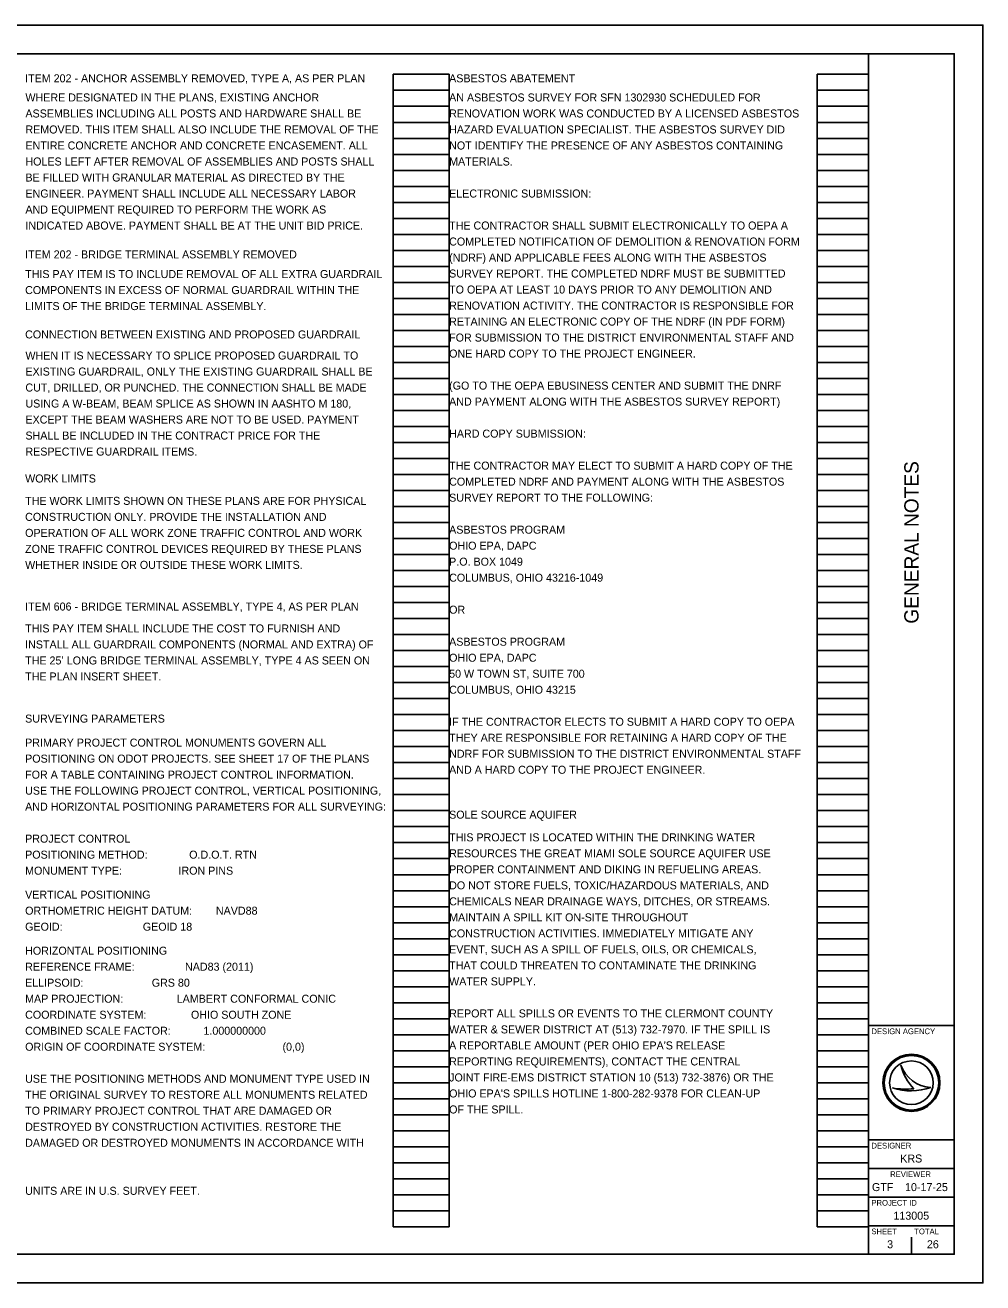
# Model space of a CAD drawing. Extents: x 0 to 78.9, y -24.2 to 22.
# Drawn here: x 17.24 to 34, y 0 to 22 of the extents above; entities that cross this region are included whole.
import ezdxf

# ---------------------------------------------------------------- set-up
doc = ezdxf.new("R2010")
doc.units = 0
for name, color, linetype in [('SH_Border', 7, 'Continuous'), ('SH_Cut_Line', 7, 'Continuous'), ('SH_Data', 7, 'Continuous'), ('SH_Text', 7, 'Continuous')]:
    doc.layers.add(name, color=color, linetype=linetype)

msp = doc.modelspace()

# ---------------------------------------------------------------- linework, layer by layer
at = {"layer": 'SH_Border'}
for p, q in [((32, 0.5), (32, 21.5)), ((32, 4.5), (33.5, 4.5)), ((32, 2.5), (33.5, 2.5)), ((32, 2), (33.5, 2)), ((32, 1.5), (33.5, 1.5)), ((32, 1), (33.5, 1))]:
    msp.add_line(p, q, dxfattribs=at)
msp.add_lwpolyline([(1.5, 21.5), (33.5, 21.5), (33.5, 0.5), (1.5, 0.5)], close=True, dxfattribs=at)
at = {"layer": 'SH_Cut_Line'}
msp.add_lwpolyline([(0, 0), (34, 0), (34, 22), (0, 22)], close=True, dxfattribs=at)
at = {"layer": 'SH_Data'}
for p, q in [((23.68, 0.98), (23.68, 21.14)), ((23.68, 21.14), (24.66, 21.14)), ((24.66, 0.98), (24.66, 21.14)), ((31.1, 0.98), (31.1, 21.14)), ((31.1, 21.14), (32, 21.14)), ((32, 0.98), (32, 21.14)), ((23.68, 20.86), (24.66, 20.86)), ((31.1, 20.86), (32, 20.86)), ((23.68, 20.58), (24.66, 20.58)), ((31.1, 20.58), (32, 20.58)), ((23.68, 20.3), (24.66, 20.3)), ((31.1, 20.3), (32, 20.3)), ((23.68, 20.02), (24.66, 20.02)), ((31.1, 20.02), (32, 20.02)), ((23.68, 19.74), (24.66, 19.74)), ((31.1, 19.74), (32, 19.74)), ((23.68, 19.46), (24.66, 19.46)), ((31.1, 19.46), (32, 19.46)), ((23.68, 19.18), (24.66, 19.18)), ((31.1, 19.18), (32, 19.18)), ((23.68, 18.9), (24.66, 18.9)), ((31.1, 18.9), (32, 18.9)), ((23.68, 18.62), (24.66, 18.62)), ((31.1, 18.62), (32, 18.62)), ((23.68, 18.34), (24.66, 18.34)), ((31.1, 18.34), (32, 18.34)), ((23.68, 18.06), (24.66, 18.06)), ((31.1, 18.06), (32, 18.06)), ((23.68, 17.78), (24.66, 17.78)), ((31.1, 17.78), (32, 17.78)), ((23.68, 17.5), (24.66, 17.5)), ((31.1, 17.5), (32, 17.5)), ((23.68, 17.22), (24.66, 17.22)), ((31.1, 17.22), (32, 17.22)), ((23.68, 16.94), (24.66, 16.94)), ((31.1, 16.94), (32, 16.94)), ((23.68, 16.66), (24.66, 16.66)), ((31.1, 16.66), (32, 16.66)), ((23.68, 16.38), (24.66, 16.38)), ((31.1, 16.38), (32, 16.38)), ((23.68, 16.1), (24.66, 16.1)), ((31.1, 16.1), (32, 16.1)), ((23.68, 15.82), (24.66, 15.82)), ((31.1, 15.82), (32, 15.82)), ((23.68, 15.54), (24.66, 15.54)), ((31.1, 15.54), (32, 15.54)), ((23.68, 15.26), (24.66, 15.26)), ((31.1, 15.26), (32, 15.26)), ((23.68, 14.98), (24.66, 14.98)), ((31.1, 14.98), (32, 14.98)), ((23.68, 14.7), (24.66, 14.7)), ((31.1, 14.7), (32, 14.7)), ((23.68, 14.42), (24.66, 14.42)), ((31.1, 14.42), (32, 14.42)), ((23.68, 14.14), (24.66, 14.14)), ((31.1, 14.14), (32, 14.14)), ((23.68, 13.86), (24.66, 13.86)), ((31.1, 13.86), (32, 13.86)), ((23.68, 13.58), (24.66, 13.58)), ((31.1, 13.58), (32, 13.58)), ((23.68, 13.3), (24.66, 13.3)), ((31.1, 13.3), (32, 13.3)), ((23.68, 13.02), (24.66, 13.02)), ((31.1, 13.02), (32, 13.02)), ((23.68, 12.74), (24.66, 12.74)), ((31.1, 12.74), (32, 12.74)), ((23.68, 12.46), (24.66, 12.46)), ((31.1, 12.46), (32, 12.46)), ((23.68, 12.18), (24.66, 12.18)), ((31.1, 12.18), (32, 12.18)), ((23.68, 11.9), (24.66, 11.9)), ((31.1, 11.9), (32, 11.9)), ((23.68, 11.62), (24.66, 11.62)), ((31.1, 11.62), (32, 11.62)), ((23.68, 11.34), (24.66, 11.34)), ((31.1, 11.34), (32, 11.34)), ((23.68, 11.06), (24.66, 11.06)), ((31.1, 11.06), (32, 11.06)), ((23.68, 10.78), (24.66, 10.78)), ((31.1, 10.78), (32, 10.78)), ((23.68, 10.5), (24.66, 10.5)), ((31.1, 10.5), (32, 10.5)), ((23.68, 10.22), (24.66, 10.22)), ((31.1, 10.22), (32, 10.22)), ((23.68, 9.94), (24.66, 9.94)), ((31.1, 9.94), (32, 9.94)), ((23.68, 9.66), (24.66, 9.66)), ((31.1, 9.66), (32, 9.66)), ((23.68, 9.38), (24.66, 9.38)), ((31.1, 9.38), (32, 9.38)), ((23.68, 9.1), (24.66, 9.1)), ((31.1, 9.1), (32, 9.1)), ((23.68, 8.82), (24.66, 8.82)), ((31.1, 8.82), (32, 8.82)), ((23.68, 8.54), (24.66, 8.54)), ((31.1, 8.54), (32, 8.54)), ((23.68, 8.26), (24.66, 8.26)), ((31.1, 8.26), (32, 8.26)), ((23.68, 7.98), (24.66, 7.98)), ((31.1, 7.98), (32, 7.98)), ((23.68, 7.7), (24.66, 7.7)), ((31.1, 7.7), (32, 7.7)), ((23.68, 7.42), (24.66, 7.42)), ((31.1, 7.42), (32, 7.42)), ((23.68, 7.14), (24.66, 7.14)), ((31.1, 7.14), (32, 7.14)), ((23.68, 6.86), (24.66, 6.86)), ((31.1, 6.86), (32, 6.86)), ((23.68, 6.58), (24.66, 6.58)), ((31.1, 6.58), (32, 6.58)), ((23.68, 6.3), (24.66, 6.3)), ((31.1, 6.3), (32, 6.3)), ((23.68, 6.02), (24.66, 6.02)), ((31.1, 6.02), (32, 6.02)), ((23.68, 5.74), (24.66, 5.74)), ((31.1, 5.74), (32, 5.74)), ((23.68, 5.46), (24.66, 5.46)), ((31.1, 5.46), (32, 5.46)), ((23.68, 5.18), (24.66, 5.18)), ((31.1, 5.18), (32, 5.18)), ((23.68, 4.9), (24.66, 4.9)), ((31.1, 4.9), (32, 4.9)), ((23.68, 4.62), (24.66, 4.62)), ((31.1, 4.62), (32, 4.62)), ((23.68, 4.34), (24.66, 4.34)), ((31.1, 4.34), (32, 4.34)), ((23.68, 4.06), (24.66, 4.06)), ((31.1, 4.06), (32, 4.06)), ((23.68, 3.78), (24.66, 3.78)), ((31.1, 3.78), (32, 3.78)), ((32.567, 3.81), (32.567, 3.81)), ((23.68, 3.5), (24.66, 3.5)), ((31.1, 3.5), (32, 3.5)), ((32.417, 3.41), (32.417, 3.41)), ((32.75, 3.5), (32.75, 3.5)), ((33.087, 3.419), (33.087, 3.419)), ((23.68, 3.22), (24.66, 3.22)), ((31.1, 3.22), (32, 3.22)), ((23.68, 2.94), (24.66, 2.94)), ((31.1, 2.94), (32, 2.94)), ((23.68, 2.66), (24.66, 2.66)), ((31.1, 2.66), (32, 2.66)), ((23.68, 2.38), (24.66, 2.38)), ((31.1, 2.38), (32, 2.38)), ((23.68, 2.1), (24.66, 2.1)), ((31.1, 2.1), (32, 2.1)), ((23.68, 1.82), (24.66, 1.82)), ((31.1, 1.82), (32, 1.82)), ((23.68, 1.54), (24.66, 1.54)), ((31.1, 1.54), (32, 1.54)), ((23.68, 1.26), (24.66, 1.26)), ((31.1, 1.26), (32, 1.26)), ((23.68, 0.98), (24.66, 0.98)), ((31.1, 0.98), (32, 0.98)), ((32.375, 0.675), (32.375, 0.675)), ((32.75, 0.5), (32.75, 0.8))]:
    msp.add_line(p, q, dxfattribs=at)
for radius in [0.5, 0.477, 0.477, 0.382]:
    msp.add_circle((32.75, 3.5), radius, dxfattribs=at)
for centre, radius, start, end in [((33.116, 3.998), 0.58, 198.9257, 198.9319), ((33.347, 3.97), 0.796, 191.6379, 191.6421), ((33.116, 3.998), 0.58, 198.9319, 267.1657), ((33.347, 3.97), 0.796, 191.6421, 226.0947), ((32.739, 4.37), 1.013, 251.4576, 290.0832), ((32.648, 4.654), 1.266, 259.4964, 259.4995), ((32.739, 4.37), 1.013, 251.4527, 251.4576), ((32.648, 4.654), 1.266, 259.4995, 276.6672)]:
    msp.add_arc(centre, radius, start, end, dxfattribs=at)

# ---------------------------------------------------------------- texts
msp.add_text('GENERAL NOTES', height=0.25, rotation=90, dxfattribs=at).set_placement((32.875, 11.531))
for s, height, p in [('DESIGN AGENCY', 0.1, (32.05, 4.35)), ('DESIGNER', 0.1, (32.05, 2.35)), ('KRS', 0.14, (32.554, 2.105)), ('REVIEWER', 0.1, (32.378, 1.85)), ('GTF', 0.14, (32.059, 1.605)), ('10-17-25', 0.14, (32.638, 1.605)), ('PROJECT ID', 0.1, (32.05, 1.35)), ('113005', 0.14, (32.435, 1.105)), ('SHEET', 0.1, (32.05, 0.85)), ('TOTAL', 0.1, (32.8, 0.85)), ('3', 0.14, (32.325, 0.605)), ('26', 0.14, (33.021, 0.605))]:
    msp.add_text(s, height=height, dxfattribs=at).set_placement(p)
at = {"layer": 'SH_Text'}
for s, p in [('ITEM 202 - ANCHOR ASSEMBLY REMOVED, TYPE A, AS PER PLAN', (17.24, 21)), ('ASBESTOS ABATEMENT', (24.66, 21)), ('WHERE DESIGNATED IN THE PLANS, EXISTING ANCHOR ', (17.245, 20.665)), ('AN ASBESTOS SURVEY FOR SFN 1302930 SCHEDULED FOR ', (24.66, 20.665)), ('ASSEMBLIES INCLUDING ALL POSTS AND HARDWARE SHALL BE ', (17.245, 20.385)), ('RENOVATION WORK WAS CONDUCTED BY A LICENSED ASBESTOS ', (24.66, 20.385)), ('REMOVED. THIS ITEM SHALL ALSO INCLUDE THE REMOVAL OF THE ', (17.245, 20.105)), ('HAZARD EVALUATION SPECIALIST. THE ASBESTOS SURVEY DID ', (24.66, 20.105)), ('ENTIRE CONCRETE ANCHOR AND CONCRETE ENCASEMENT. ALL ', (17.245, 19.825)), ('NOT IDENTIFY THE PRESENCE OF ANY ASBESTOS CONTAINING ', (24.66, 19.825)), ('HOLES LEFT AFTER REMOVAL OF ASSEMBLIES AND POSTS SHALL ', (17.245, 19.545)), ('MATERIALS.', (24.66, 19.545)), ('BE FILLED WITH GRANULAR MATERIAL AS DIRECTED BY THE ', (17.245, 19.265)), ('ENGINEER. PAYMENT SHALL INCLUDE ALL NECESSARY LABOR ', (17.245, 18.985)), ('ELECTRONIC SUBMISSION:', (24.66, 18.985)), ('AND EQUIPMENT REQUIRED TO PERFORM THE WORK AS ', (17.245, 18.705)), ('INDICATED ABOVE. PAYMENT SHALL BE AT THE UNIT BID PRICE.', (17.245, 18.425)), ('THE CONTRACTOR SHALL SUBMIT ELECTRONICALLY TO OEPA A ', (24.66, 18.425)), ('COMPLETED NOTIFICATION OF DEMOLITION & RENOVATION FORM ', (24.66, 18.145)), ('ITEM 202 - BRIDGE TERMINAL ASSEMBLY REMOVED', (17.24, 17.92)), ('(NDRF) AND APPLICABLE FEES ALONG WITH THE ASBESTOS ', (24.66, 17.865)), ('THIS PAY ITEM IS TO INCLUDE REMOVAL OF ALL EXTRA GUARDRAIL ', (17.24, 17.576)), ('SURVEY REPORT. THE COMPLETED NDRF MUST BE SUBMITTED ', (24.66, 17.585)), ('COMPONENTS IN EXCESS OF NORMAL GUARDRAIL WITHIN THE ', (17.24, 17.296)), ('TO OEPA AT LEAST 10 DAYS PRIOR TO ANY DEMOLITION AND ', (24.66, 17.305)), ('RENOVATION ACTIVITY. THE CONTRACTOR IS RESPONSIBLE FOR ', (24.66, 17.025)), ('LIMITS OF THE BRIDGE TERMINAL ASSEMBLY. ', (17.24, 17.016)), ('RETAINING AN ELECTRONIC COPY OF THE NDRF (IN PDF FORM) ', (24.66, 16.745)), ('CONNECTION BETWEEN EXISTING AND PROPOSED GUARDRAIL', (17.24, 16.52)), ('FOR SUBMISSION TO THE DISTRICT ENVIRONMENTAL STAFF AND ', (24.66, 16.465)), ('WHEN IT IS NECESSARY TO SPLICE PROPOSED GUARDRAIL TO ', (17.245, 16.151)), ('ONE HARD COPY TO THE PROJECT ENGINEER.', (24.66, 16.185)), ('EXISTING GUARDRAIL, ONLY THE EXISTING GUARDRAIL SHALL BE ', (17.245, 15.871)), ('CUT, DRILLED, OR PUNCHED. THE CONNECTION SHALL BE MADE ', (17.245, 15.591)), ('(GO TO THE OEPA EBUSINESS CENTER AND SUBMIT THE DNRF ', (24.66, 15.625)), ('USING A W-BEAM, BEAM SPLICE AS SHOWN IN AASHTO M 180, ', (17.245, 15.311)), ('AND PAYMENT ALONG WITH THE ASBESTOS SURVEY REPORT)', (24.66, 15.345)), ('EXCEPT THE BEAM WASHERS ARE NOT TO BE USED. PAYMENT ', (17.245, 15.031)), ('SHALL BE INCLUDED IN THE CONTRACT PRICE FOR THE ', (17.245, 14.751)), ('HARD COPY SUBMISSION:', (24.66, 14.785)), ('RESPECTIVE GUARDRAIL ITEMS.', (17.245, 14.471)), ('THE CONTRACTOR MAY ELECT TO SUBMIT A HARD COPY OF THE ', (24.66, 14.225)), ('WORK LIMITS', (17.24, 14)), ('COMPLETED NDRF AND PAYMENT ALONG WITH THE ASBESTOS ', (24.66, 13.945)), ('THE WORK LIMITS SHOWN ON THESE PLANS ARE FOR PHYSICAL ', (17.24, 13.609)), ('SURVEY REPORT TO THE FOLLOWING:', (24.66, 13.665)), ('CONSTRUCTION ONLY. PROVIDE THE INSTALLATION AND ', (17.24, 13.329)), ('ASBESTOS PROGRAM', (24.66, 13.105)), ('OPERATION OF ALL WORK ZONE TRAFFIC CONTROL AND WORK ', (17.24, 13.049)), ('ZONE TRAFFIC CONTROL DEVICES REQUIRED BY THESE PLANS ', (17.24, 12.769)), ('OHIO EPA, DAPC', (24.66, 12.825)), ('WHETHER INSIDE OR OUTSIDE THESE WORK LIMITS. ', (17.24, 12.489)), ('P.O. BOX 1049', (24.66, 12.545)), ('COLUMBUS, OHIO 43216-1049', (24.66, 12.265)), ('ITEM 606 - BRIDGE TERMINAL ASSEMBLY, TYPE 4, AS PER PLAN', (17.24, 11.76)), ('OR ', (24.66, 11.705)), ('THIS PAY ITEM SHALL INCLUDE THE COST TO FURNISH AND ', (17.24, 11.377)), ('INSTALL ALL GUARDRAIL COMPONENTS (NORMAL AND EXTRA) OF ', (17.24, 11.097)), ('ASBESTOS PROGRAM ', (24.66, 11.145)), ('OHIO EPA, DAPC ', (24.66, 10.865)), ('THE 25’ LONG BRIDGE TERMINAL ASSEMBLY, TYPE 4 AS SEEN ON ', (17.24, 10.817)), ('THE PLAN INSERT SHEET.', (17.24, 10.537)), ('50 W TOWN ST, SUITE 700', (24.66, 10.585)), ('COLUMBUS, OHIO 43215', (24.66, 10.305)), ('SURVEYING PARAMETERS', (17.24, 9.8)), ('IF THE CONTRACTOR ELECTS TO SUBMIT A HARD COPY TO OEPA ', (24.66, 9.745)), ('PRIMARY PROJECT CONTROL MONUMENTS GOVERN ALL', (17.24, 9.38)), ('THEY ARE RESPONSIBLE FOR RETAINING A HARD COPY OF THE ', (24.66, 9.465)), ('POSITIONING ON ODOT PROJECTS. SEE SHEET 17 OF THE PLANS', (17.24, 9.1)), ('NDRF FOR SUBMISSION TO THE DISTRICT ENVIRONMENTAL STAFF ', (24.66, 9.185)), ('AND A HARD COPY TO THE PROJECT ENGINEER.', (24.66, 8.905)), ('FOR A TABLE CONTAINING PROJECT CONTROL INFORMATION.', (17.24, 8.82)), ('USE THE FOLLOWING PROJECT CONTROL, VERTICAL POSITIONING,', (17.24, 8.54)), ('AND HORIZONTAL POSITIONING PARAMETERS FOR ALL SURVEYING:', (17.24, 8.26)), ('SOLE SOURCE AQUIFER', (24.66, 8.12)), ('PROJECT CONTROL', (17.24, 7.7)), ('THIS PROJECT IS LOCATED WITHIN THE DRINKING WATER ', (24.66, 7.723)), ('POSITIONING METHOD:              O.D.O.T. RTN', (17.24, 7.42)), ('RESOURCES THE GREAT MIAMI SOLE SOURCE AQUIFER USE ', (24.66, 7.443)), ('MONUMENT TYPE:                   IRON PINS', (17.24, 7.14)), ('PROPER CONTAINMENT AND DIKING IN REFUELING AREAS. ', (24.66, 7.163)), ('VERTICAL POSITIONING', (17.24, 6.72)), ('DO NOT STORE FUELS, TOXIC/HAZARDOUS MATERIALS, AND ', (24.66, 6.883)), ('CHEMICALS NEAR DRAINAGE WAYS, DITCHES, OR STREAMS. ', (24.66, 6.603)), ('ORTHOMETRIC HEIGHT DATUM:        NAVD88', (17.24, 6.44)), ('MAINTAIN A SPILL KIT ON-SITE THROUGHOUT ', (24.66, 6.323)), ('GEOID:                           GEOID 18', (17.24, 6.16)), ('CONSTRUCTION ACTIVITIES. IMMEDIATELY MITIGATE ANY ', (24.66, 6.043)), ('HORIZONTAL POSITIONING', (17.24, 5.74)), ('EVENT, SUCH AS A SPILL OF FUELS, OILS, OR CHEMICALS, ', (24.66, 5.763)), ('REFERENCE FRAME:                 NAD83 (2011)', (17.24, 5.46)), ('THAT COULD THREATEN TO CONTAMINATE THE DRINKING ', (24.66, 5.483)), ('ELLIPSOID:                       GRS 80', (17.24, 5.18)), ('WATER SUPPLY. ', (24.66, 5.203)), ('MAP PROJECTION:                  LAMBERT CONFORMAL CONIC', (17.24, 4.9)), ('COORDINATE SYSTEM:               OHIO SOUTH ZONE', (17.24, 4.62)), ('REPORT ALL SPILLS OR EVENTS TO THE CLERMONT COUNTY ', (24.66, 4.643)), ('COMBINED SCALE FACTOR:           1.000000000', (17.24, 4.34)), ('WATER & SEWER DISTRICT AT (513) 732-7970. IF THE SPILL IS ', (24.66, 4.363)), ('ORIGIN OF COORDINATE SYSTEM:                          (0,0)', (17.24, 4.06)), ("A REPORTABLE AMOUNT (PER OHIO EPA'S RELEASE ", (24.66, 4.083)), ('REPORTING REQUIREMENTS), CONTACT THE CENTRAL ', (24.66, 3.803)), ('USE THE POSITIONING METHODS AND MONUMENT TYPE USED IN', (17.24, 3.5)), ('JOINT FIRE-EMS DISTRICT STATION 10 (513) 732-3876) OR THE ', (24.66, 3.523)), ('THE ORIGINAL SURVEY TO RESTORE ALL MONUMENTS RELATED', (17.24, 3.22)), ("OHIO EPA'S SPILLS HOTLINE 1-800-282-9378 FOR CLEAN-UP ", (24.66, 3.243)), ('TO PRIMARY PROJECT CONTROL THAT ARE DAMAGED OR', (17.24, 2.94)), ('OF THE SPILL. ', (24.66, 2.963)), ('DESTROYED BY CONSTRUCTION ACTIVITIES. RESTORE THE', (17.24, 2.66)), ('DAMAGED OR DESTROYED MONUMENTS IN ACCORDANCE WITH', (17.24, 2.38)), ('UNITS ARE IN U.S. SURVEY FEET.', (17.24, 1.54))]:
    msp.add_text(s, height=0.14, dxfattribs=at).set_placement(p)

doc.saveas('drawing.dxf')
